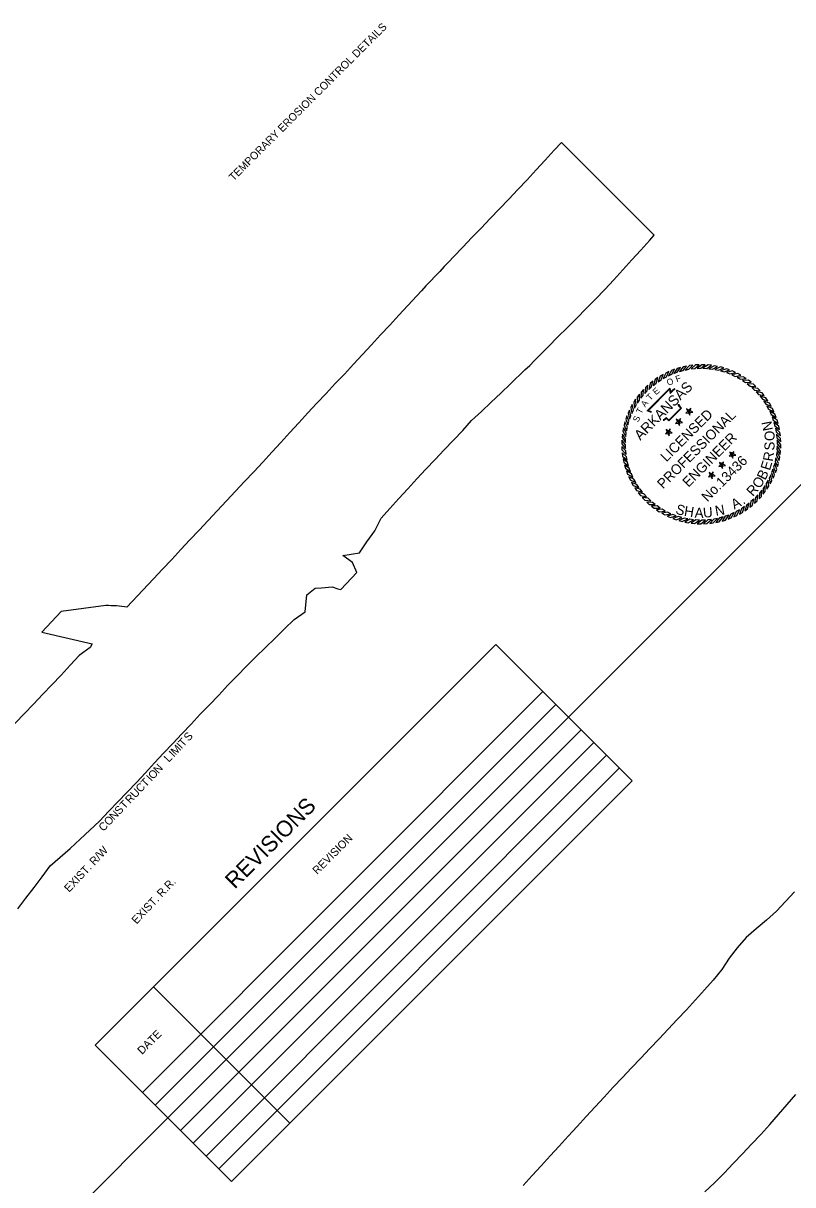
# Model space of a CAD drawing. Extents: x 1377291 to 1378879, y 1932405 to 1934097.
# Drawn here: x 1377982 to 1378559, y 1933226 to 1934097 of the extents above; entities that cross this region are included whole.
import ezdxf

# ---------------------------------------------------------------- set-up
doc = ezdxf.new("R2010")
doc.units = 0
for name, color, linetype in [('1', 7, 'Continuous'), ('Default', 7, 'Continuous'), ('G-ANNO-SYMB', 7, 'Continuous'), ('R_Draft', 7, 'Continuous'), ('R_NO PLOT', 7, 'Continuous')]:
    doc.layers.add(name, color=color, linetype=linetype)

msp = doc.modelspace()

# ---------------------------------------------------------------- linework, layer by layer
at = {"layer": '1'}
for p, q in [((1378390.79, 1933576.64), (1378603.63, 1933789.47)), ((1377887.91, 1933073.76), (1378090.27, 1933276.12))]:
    msp.add_line(p, q, dxfattribs=at)
at = {"layer": 'Default'}
for p, q in [((1378035.83, 1933330.56), (1378336.35, 1933631.08)), ((1378336.35, 1933631.08), (1378438.52, 1933528.91)), ((1378071.18, 1933295.21), (1378371.7, 1933595.73)), ((1378080.73, 1933285.66), (1378381.25, 1933586.18)), ((1378090.27, 1933276.12), (1378390.79, 1933576.64)), ((1378099.82, 1933266.57), (1378400.34, 1933567.09)), ((1378099.82, 1933266.57), (1378400.34, 1933567.09)), ((1378109.37, 1933257.02), (1378409.89, 1933557.55)), ((1378118.91, 1933247.48), (1378419.43, 1933548)), ((1378128.46, 1933237.93), (1378428.98, 1933538.45)), ((1378138, 1933228.39), (1378438.52, 1933528.91)), ((1378079.53, 1933374.27), (1378181.71, 1933272.09)), ((1378035.83, 1933330.56), (1378138, 1933228.39))]:
    msp.add_line(p, q, dxfattribs=at)
at = {"layer": 'G-ANNO-SYMB'}
for points in [[(1378466.07, 1933835.66), (1378463.76, 1933834.56), (1378461.82, 1933830.41), (1378464.25, 1933831.75)], [(1378470.42, 1933837.4), (1378468.02, 1933836.49), (1378465.77, 1933832.51), (1378468.3, 1933833.65)], [(1378474.89, 1933838.8), (1378472.43, 1933838.08), (1378469.87, 1933834.29), (1378472.48, 1933835.23)], [(1378479.46, 1933839.85), (1378476.95, 1933839.32), (1378474.1, 1933835.74), (1378476.77, 1933836.47)], [(1378484.09, 1933840.53), (1378481.55, 1933840.2), (1378478.43, 1933836.86), (1378481.15, 1933837.38)], [(1378488.77, 1933840.85), (1378486.2, 1933840.72), (1378482.83, 1933837.63), (1378485.59, 1933837.94)], [(1378493.45, 1933840.8), (1378490.89, 1933840.87), (1378487.28, 1933838.06), (1378490.05, 1933838.14)], [(1378498.12, 1933840.38), (1378495.56, 1933840.66), (1378491.75, 1933838.13), (1378494.52, 1933838)], [(1378502.73, 1933839.6), (1378500.21, 1933840.07), (1378496.21, 1933837.86), (1378498.96, 1933837.51)], [(1378507.28, 1933838.46), (1378504.8, 1933839.13), (1378500.64, 1933837.23), (1378503.35, 1933836.67)], [(1378511.72, 1933836.96), (1378509.3, 1933837.82), (1378505, 1933836.26), (1378507.67, 1933835.49)], [(1378516.03, 1933835.12), (1378513.68, 1933836.17), (1378509.28, 1933834.95), (1378511.87, 1933833.97)], [(1378520.18, 1933832.95), (1378517.92, 1933834.18), (1378513.44, 1933833.31), (1378515.94, 1933832.13)], [(1378450.44, 1933825.45), (1378448.58, 1933823.69), (1378448.02, 1933819.15), (1378449.92, 1933821.17)], [(1378454.04, 1933828.46), (1378452.04, 1933826.85), (1378451.13, 1933822.37), (1378453.18, 1933824.23)], [(1378457.86, 1933831.17), (1378455.74, 1933829.72), (1378454.48, 1933825.33), (1378456.67, 1933827.03)], [(1378461.88, 1933833.57), (1378459.65, 1933832.3), (1378458.05, 1933828.01), (1378460.37, 1933829.54)], [(1378524.14, 1933830.46), (1378522, 1933831.86), (1378517.45, 1933831.35), (1378519.86, 1933829.97)], [(1378527.9, 1933827.67), (1378525.87, 1933829.23), (1378521.3, 1933829.07), (1378523.6, 1933827.52)], [(1378531.43, 1933824.59), (1378529.53, 1933826.31), (1378524.96, 1933826.51), (1378527.13, 1933824.78)], [(1378444.02, 1933818.65), (1378442.45, 1933816.62), (1378442.61, 1933812.05), (1378444.17, 1933814.34)], [(1378447.1, 1933822.18), (1378445.38, 1933820.27), (1378445.18, 1933815.71), (1378446.91, 1933817.87)], [(1378534.71, 1933821.24), (1378532.95, 1933823.11), (1378528.41, 1933823.66), (1378530.43, 1933821.77)], [(1378537.71, 1933817.65), (1378536.1, 1933819.64), (1378531.62, 1933820.55), (1378533.49, 1933818.51)], [(1378540.43, 1933813.83), (1378538.98, 1933815.94), (1378534.58, 1933817.2), (1378536.28, 1933815.02)], [(1378438.73, 1933810.92), (1378437.5, 1933808.67), (1378438.38, 1933804.18), (1378439.56, 1933806.69)], [(1378441.22, 1933814.89), (1378439.82, 1933812.74), (1378440.34, 1933808.2), (1378441.71, 1933810.6)], [(1378481.39, 1933805.73), (1378482.31, 1933806.2), (1378482.62, 1933808.16), (1378481.22, 1933806.76)], [(1378542.83, 1933809.81), (1378541.55, 1933812.03), (1378537.27, 1933813.63), (1378538.79, 1933811.32)], [(1378544.91, 1933805.61), (1378543.81, 1933807.93), (1378539.67, 1933809.86), (1378541.01, 1933807.43)], [(1378434.72, 1933802.46), (1378433.86, 1933800.04), (1378435.42, 1933795.75), (1378436.2, 1933798.41)], [(1378436.56, 1933806.77), (1378435.51, 1933804.43), (1378436.73, 1933800.02), (1378437.71, 1933802.61)], [(1378473.67, 1933798.01), (1378473.51, 1933799.04), (1378471.74, 1933799.94), (1378472.64, 1933798.18)], [(1378473.67, 1933798.01), (1378474.6, 1933798.49), (1378474.91, 1933800.44), (1378473.51, 1933799.04)], [(1378481.39, 1933805.73), (1378480.36, 1933805.89), (1378478.96, 1933804.49), (1378480.91, 1933804.8)], [(1378481.39, 1933805.73), (1378481.22, 1933806.76), (1378479.46, 1933807.65), (1378480.36, 1933805.89)], [(1378481.39, 1933805.73), (1378480.91, 1933804.8), (1378481.81, 1933803.03), (1378482.12, 1933804.99)], [(1378481.39, 1933805.73), (1378482.12, 1933804.99), (1378484.08, 1933805.3), (1378482.31, 1933806.2)], [(1378546.66, 1933801.26), (1378545.75, 1933803.66), (1378541.77, 1933805.91), (1378542.91, 1933803.39)], [(1378548.06, 1933796.79), (1378547.34, 1933799.25), (1378543.55, 1933801.81), (1378544.49, 1933799.2)], [(1378432.09, 1933793.48), (1378431.61, 1933790.96), (1378433.83, 1933786.96), (1378434.18, 1933789.71)], [(1378433.23, 1933798.02), (1378432.56, 1933795.54), (1378434.45, 1933791.38), (1378435.02, 1933794.1)], [(1378465.96, 1933790.3), (1378464.93, 1933790.46), (1378463.53, 1933789.06), (1378465.49, 1933789.37)], [(1378465.96, 1933790.3), (1378465.8, 1933791.33), (1378464.03, 1933792.23), (1378464.93, 1933790.46)], [(1378465.96, 1933790.3), (1378465.49, 1933789.37), (1378466.39, 1933787.6), (1378466.7, 1933789.56)], [(1378465.96, 1933790.3), (1378466.89, 1933790.77), (1378467.2, 1933792.73), (1378465.8, 1933791.33)], [(1378465.96, 1933790.3), (1378466.7, 1933789.56), (1378468.65, 1933789.87), (1378466.89, 1933790.77)], [(1378473.67, 1933798.01), (1378472.64, 1933798.18), (1378471.24, 1933796.77), (1378473.2, 1933797.08)], [(1378473.67, 1933798.01), (1378473.2, 1933797.08), (1378474.1, 1933795.32), (1378474.41, 1933797.28)], [(1378473.67, 1933798.01), (1378474.41, 1933797.28), (1378476.37, 1933797.59), (1378474.6, 1933798.49)], [(1378549.11, 1933792.23), (1378548.58, 1933794.74), (1378545, 1933797.58), (1378545.73, 1933794.91)], [(1378549.79, 1933787.59), (1378549.46, 1933790.14), (1378546.12, 1933793.26), (1378546.64, 1933790.53)], [(1378430.89, 1933784.19), (1378430.81, 1933781.63), (1378433.63, 1933778.03), (1378433.54, 1933780.8)], [(1378431.3, 1933788.86), (1378431.03, 1933786.31), (1378433.55, 1933782.49), (1378433.68, 1933785.26)], [(1378550.11, 1933782.92), (1378549.98, 1933785.48), (1378546.89, 1933788.85), (1378547.19, 1933786.1)], [(1378550.06, 1933778.23), (1378550.13, 1933780.8), (1378547.31, 1933784.4), (1378547.4, 1933781.63)], [(1378430.84, 1933779.51), (1378430.96, 1933776.95), (1378434.05, 1933773.58), (1378433.75, 1933776.33)], [(1378431.15, 1933774.84), (1378431.48, 1933772.29), (1378434.83, 1933769.17), (1378434.31, 1933771.89)], [(1378513.69, 1933773.42), (1378512.66, 1933773.59), (1378511.26, 1933772.19), (1378513.22, 1933772.5)], [(1378513.69, 1933773.42), (1378513.53, 1933774.45), (1378511.76, 1933775.35), (1378512.66, 1933773.59)], [(1378513.69, 1933773.42), (1378513.22, 1933772.5), (1378514.12, 1933770.73), (1378514.43, 1933772.69)], [(1378513.69, 1933773.42), (1378514.62, 1933773.9), (1378514.93, 1933775.85), (1378513.53, 1933774.45)], [(1378513.69, 1933773.42), (1378514.43, 1933772.69), (1378516.38, 1933773), (1378514.62, 1933773.9)], [(1378548.86, 1933768.95), (1378549.33, 1933771.47), (1378547.11, 1933775.47), (1378546.77, 1933772.72)], [(1378549.64, 1933773.57), (1378549.91, 1933776.12), (1378547.39, 1933779.93), (1378547.26, 1933777.16)], [(1378431.84, 1933770.2), (1378432.36, 1933767.69), (1378435.94, 1933764.84), (1378435.21, 1933767.52)], [(1378432.88, 1933765.63), (1378433.6, 1933763.17), (1378437.4, 1933760.62), (1378436.46, 1933763.22)], [(1378505.97, 1933765.71), (1378504.95, 1933765.87), (1378503.54, 1933764.47), (1378505.5, 1933764.78)], [(1378505.97, 1933765.71), (1378505.81, 1933766.74), (1378504.05, 1933767.64), (1378504.95, 1933765.87)], [(1378505.97, 1933765.71), (1378505.5, 1933764.78), (1378506.4, 1933763.02), (1378506.71, 1933764.97)], [(1378505.97, 1933765.71), (1378506.9, 1933766.18), (1378507.21, 1933768.14), (1378505.81, 1933766.74)], [(1378505.97, 1933765.71), (1378506.71, 1933764.97), (1378508.67, 1933765.28), (1378506.9, 1933766.18)], [(1378546.22, 1933759.97), (1378547.08, 1933762.38), (1378545.52, 1933766.68), (1378544.74, 1933764.02)], [(1378547.71, 1933764.41), (1378548.38, 1933766.88), (1378546.49, 1933771.04), (1378545.93, 1933768.33)], [(1378434.28, 1933761.16), (1378435.2, 1933758.77), (1378439.18, 1933756.51), (1378438.03, 1933759.04)], [(1378436.03, 1933756.82), (1378437.13, 1933754.5), (1378441.27, 1933752.57), (1378439.94, 1933755)], [(1378498.26, 1933758), (1378497.23, 1933758.16), (1378495.83, 1933756.76), (1378497.79, 1933757.07)], [(1378498.26, 1933758), (1378498.1, 1933759.03), (1378496.33, 1933759.92), (1378497.23, 1933758.16)], [(1378498.26, 1933758), (1378497.79, 1933757.07), (1378498.69, 1933755.3), (1378499, 1933757.26)], [(1378498.26, 1933758), (1378499.19, 1933758.47), (1378499.5, 1933760.43), (1378498.1, 1933759.03)], [(1378498.26, 1933758), (1378499, 1933757.26), (1378500.95, 1933757.57), (1378499.19, 1933758.47)], [(1378542.21, 1933751.51), (1378543.44, 1933753.76), (1378542.57, 1933758.25), (1378541.39, 1933755.74)], [(1378544.38, 1933755.66), (1378545.43, 1933758), (1378544.21, 1933762.41), (1378543.23, 1933759.81)], [(1378438.11, 1933752.62), (1378439.39, 1933750.4), (1378443.67, 1933748.79), (1378442.15, 1933751.11)], [(1378440.51, 1933748.6), (1378441.96, 1933746.48), (1378446.36, 1933745.22), (1378444.66, 1933747.41)], [(1378533.84, 1933740.25), (1378535.57, 1933742.15), (1378535.77, 1933746.72), (1378534.03, 1933744.56)], [(1378536.93, 1933743.78), (1378538.49, 1933745.81), (1378538.33, 1933750.38), (1378536.77, 1933748.09)], [(1378539.72, 1933747.54), (1378541.12, 1933749.69), (1378540.6, 1933754.23), (1378539.23, 1933751.82)], [(1378443.23, 1933744.78), (1378444.84, 1933742.78), (1378449.32, 1933741.87), (1378447.45, 1933743.92)], [(1378446.23, 1933741.19), (1378447.99, 1933739.32), (1378452.53, 1933738.77), (1378450.51, 1933740.66)], [(1378526.9, 1933733.97), (1378528.9, 1933735.58), (1378529.81, 1933740.06), (1378527.76, 1933738.2)], [(1378530.5, 1933736.97), (1378532.36, 1933738.74), (1378532.92, 1933743.27), (1378531.02, 1933741.25)], [(1378449.51, 1933737.84), (1378451.41, 1933736.12), (1378455.98, 1933735.92), (1378453.82, 1933737.65)], [(1378453.04, 1933734.76), (1378455.07, 1933733.19), (1378459.64, 1933733.35), (1378457.35, 1933734.91)], [(1378456.8, 1933731.97), (1378458.95, 1933730.56), (1378463.49, 1933731.08), (1378461.08, 1933732.45)], [(1378460.77, 1933729.48), (1378463.02, 1933728.25), (1378467.51, 1933729.12), (1378465, 1933730.3)], [(1378510.52, 1933725.02), (1378512.92, 1933725.94), (1378515.17, 1933729.92), (1378512.64, 1933728.78)], [(1378514.87, 1933726.77), (1378517.19, 1933727.87), (1378519.12, 1933732.01), (1378516.69, 1933730.68)], [(1378519.06, 1933728.85), (1378521.29, 1933730.13), (1378522.89, 1933734.41), (1378520.57, 1933732.89)], [(1378523.08, 1933731.26), (1378525.2, 1933732.71), (1378526.46, 1933737.1), (1378524.27, 1933735.4)], [(1378464.92, 1933727.3), (1378467.26, 1933726.26), (1378471.66, 1933727.48), (1378469.07, 1933728.46)], [(1378469.22, 1933725.47), (1378471.64, 1933724.6), (1378475.94, 1933726.17), (1378473.28, 1933726.94)], [(1378473.66, 1933723.97), (1378476.14, 1933723.3), (1378480.3, 1933725.2), (1378477.59, 1933725.76)], [(1378478.21, 1933722.83), (1378480.73, 1933722.36), (1378484.73, 1933724.57), (1378481.98, 1933724.92)], [(1378482.83, 1933722.05), (1378485.38, 1933721.77), (1378489.19, 1933724.3), (1378486.42, 1933724.43)], [(1378487.49, 1933721.63), (1378490.06, 1933721.56), (1378493.66, 1933724.37), (1378490.89, 1933724.28)], [(1378492.18, 1933721.58), (1378494.74, 1933721.71), (1378498.11, 1933724.8), (1378495.35, 1933724.49)], [(1378496.85, 1933721.9), (1378499.39, 1933722.23), (1378502.51, 1933725.57), (1378499.79, 1933725.05)], [(1378501.48, 1933722.58), (1378503.99, 1933723.11), (1378506.84, 1933726.69), (1378504.17, 1933725.95)], [(1378506.05, 1933723.62), (1378508.51, 1933724.35), (1378511.07, 1933728.14), (1378508.46, 1933727.2)]]:
    msp.add_lwpolyline(points, close=True, dxfattribs=at)
for points in [[(1378453.09, 1933805.07), (1378449.98, 1933806.22), (1378466.99, 1933823.24), (1378467.35, 1933820.04), (1378468.49, 1933821.21), (1378469.45, 1933822.19), (1378470.52, 1933823.05)], [(1378453.23, 1933805.43), (1378450.67, 1933806.37), (1378466.7, 1933822.42), (1378467.06, 1933819.2), (1378468.77, 1933820.94), (1378469.7, 1933821.9), (1378470.75, 1933822.75)], [(1378473.58, 1933811.29), (1378473.52, 1933810.77), (1378473.78, 1933810.32), (1378474.56, 1933809.34), (1378475.74, 1933808.16), (1378466.24, 1933798.66), (1378464.65, 1933800.25), (1378464.3, 1933800.61), (1378463.8, 1933800.34), (1378462.45, 1933798.99), (1378461.84, 1933799.11)], [(1378473.2, 1933811.33), (1378473.13, 1933810.68), (1378473.46, 1933810.1), (1378474.28, 1933809.08), (1378475.2, 1933808.16), (1378466.24, 1933799.2), (1378464.92, 1933800.52), (1378464.37, 1933801.07), (1378463.57, 1933800.65), (1378462.32, 1933799.4), (1378461.92, 1933799.49)]]:
    msp.add_lwpolyline(points, dxfattribs=at)
at = {"layer": 'R_NO PLOT'}
for p, q in [((1378043.74, 1933660.2), (1378010.12, 1933655.71)), ((1378033.6, 1933631.58), (1378032.08, 1933628.8))]:
    msp.add_line(p, q, dxfattribs=at)
for points in [[(1378455.1, 1933938), (1378385.59, 1934007.51), (1378380.13, 1934001.59), (1378373.33, 1933994.25), (1378366.54, 1933986.91), (1378359.74, 1933979.57), (1378352.94, 1933972.25), (1378346.03, 1933965.01), (1378339.12, 1933957.78), (1378332.2, 1933950.57), (1378325.28, 1933943.35), (1378318.38, 1933936.11), (1378311.49, 1933928.86), (1378304.6, 1933921.62), (1378301.15, 1933917.99)], [(1378221.56, 1933697.7), (1378233.93, 1933699.8), (1378239.64, 1933708.16), (1378245.48, 1933716.39), (1378250.21, 1933725.67), (1378256.89, 1933733.12), (1378263.67, 1933740.47), (1378270.39, 1933747.87), (1378277.11, 1933755.28), (1378283.89, 1933762.63), (1378290.85, 1933769.82), (1378297.68, 1933777.11), (1378304.59, 1933784.35), (1378311.48, 1933791.59), (1378318.16, 1933799.04), (1378325.48, 1933805.88), (1378332.77, 1933812.75), (1378340.06, 1933819.63), (1378347.34, 1933826.5), (1378350.95, 1933829.98), (1378354.58, 1933833.42), (1378358.2, 1933836.89), (1378361.79, 1933840.37), (1378365.33, 1933843.91), (1378368.85, 1933847.46), (1378372.37, 1933851.01), (1378375.9, 1933854.56), (1378382.94, 1933861.67), (1378389.99, 1933868.76), (1378397.05, 1933875.85), (1378404.1, 1933882.95), (1378411.16, 1933890.04), (1378418.09, 1933897.24), (1378424.85, 1933904.61), (1378431.6, 1933911.99), (1378438.36, 1933919.37), (1378445.11, 1933926.75), (1378451.78, 1933934.2), (1378455.1, 1933938)], [(1378301.15, 1933917.99), (1378297.68, 1933914.4), (1378294.2, 1933910.8), (1378290.73, 1933907.2), (1378287.32, 1933903.54), (1378283.92, 1933899.88), (1378280.52, 1933896.22), (1378277.11, 1933892.55), (1378270.31, 1933885.22), (1378263.5, 1933877.9), (1378256.7, 1933870.57), (1378249.93, 1933863.21), (1378243.16, 1933855.85), (1378236.39, 1933848.49), (1378229.61, 1933841.13), (1378222.85, 1933833.76), (1378215.83, 1933826.64), (1378208.95, 1933819.38), (1378202.15, 1933812.05), (1378195.38, 1933804.69), (1378188.58, 1933797.35), (1378181.79, 1933790.02), (1378175.04, 1933782.64), (1378168.29, 1933775.25), (1378161.55, 1933767.86), (1378154.74, 1933760.55), (1378147.9, 1933753.24), (1378141.06, 1933745.95), (1378134.21, 1933738.66), (1378127.37, 1933731.38), (1378120.52, 1933724.09), (1378113.67, 1933716.8), (1378106.84, 1933709.49), (1378099.99, 1933702.21), (1378093.16, 1933694.9), (1378086.33, 1933687.6), (1378079.51, 1933680.29), (1378059.62, 1933659.04)], [(1378232.15, 1933685.1), (1378228.83, 1933692.53), (1378221.56, 1933697.7)], [(1378205.53, 1933673.59), (1378213.58, 1933674.24), (1378217.76, 1933672.69), (1378219.95, 1933672.17), (1378232.15, 1933685.1)], [(1378194.5, 1933668.24), (1378200.76, 1933673.22), (1378205.53, 1933673.59)], [(1377977.76, 1933432.8), (1377983.83, 1933440.81), (1377989.89, 1933448.84), (1377996.09, 1933456.74), (1378001.89, 1933465.01), (1378009.56, 1933471.52), (1378017.08, 1933478.18), (1378024.39, 1933485.03), (1378031.76, 1933491.83), (1378039.05, 1933498.7), (1378045.93, 1933505.96), (1378052.83, 1933513.2), (1378059.77, 1933520.4), (1378066.64, 1933527.66), (1378073.59, 1933534.85), (1378080.32, 1933542.25), (1378087.13, 1933549.58), (1378094.04, 1933556.81), (1378100.84, 1933564.14), (1378107.69, 1933571.42), (1378114.43, 1933578.81), (1378121.48, 1933585.91), (1378128.41, 1933593.12), (1378135.23, 1933600.44), (1378142.2, 1933607.61), (1378149.18, 1933614.77), (1378156.31, 1933621.79), (1378163.45, 1933628.81), (1378170.66, 1933635.75), (1378177.82, 1933642.74), (1378185, 1933649.72), (1378193.33, 1933655.62), (1378194.5, 1933668.24)], [(1378010.12, 1933655.71), (1377995.68, 1933640.37), (1378033.6, 1933631.58)], [(1378032.08, 1933628.8), (1378023.82, 1933622.84), (1378017.02, 1933615.51), (1378010.21, 1933608.18), (1378003.34, 1933600.92), (1377996.38, 1933593.74), (1377989.58, 1933586.41), (1377982.61, 1933579.24), (1377975.66, 1933572.04), (1377968.8, 1933564.76), (1377962.03, 1933557.41), (1377955.24, 1933550.06), (1377948.47, 1933542.7), (1377941.65, 1933535.39)], [(1378560.44, 1933445.69), (1378553.61, 1933438.39), (1378546.8, 1933431.06), (1378539.34, 1933424.35), (1378531.76, 1933417.75), (1378524.08, 1933411.25), (1378517.49, 1933403.71), (1378511.35, 1933395.76), (1378505.8, 1933387.25), (1378499.47, 1933379.48), (1378492.8, 1933372.03), (1378486.14, 1933364.56), (1378479.36, 1933357.21), (1378472.49, 1933349.94), (1378465.63, 1933342.67), (1378458.81, 1933335.35), (1378451.96, 1933328.06), (1378445.06, 1933320.83), (1378438.17, 1933313.58), (1378431.31, 1933306.3), (1378424.45, 1933299.03), (1378417.59, 1933291.75), (1378410.81, 1933284.4), (1378404.03, 1933277.05), (1378397.25, 1933269.7), (1378390.49, 1933262.33), (1378383.75, 1933254.94), (1378377, 1933247.56), (1378370.27, 1933240.16), (1378363.52, 1933232.79), (1378356.74, 1933225.43)], [(1378493.15, 1933220.69), (1378500.49, 1933227.52), (1378507.57, 1933234.59), (1378514.46, 1933241.83), (1378521.37, 1933249.07), (1378528.22, 1933256.35), (1378535.13, 1933263.58), (1378541.8, 1933271.04), (1378548.36, 1933278.59), (1378554.92, 1933286.15), (1378561.49, 1933293.7)]]:
    msp.add_lwpolyline(points, dxfattribs=at)
msp.add_arc((1378045, 1933568.21), 91.99, 80.85932, 90.78815, dxfattribs=at)

# ---------------------------------------------------------------- texts
at = {"layer": '1'}
msp.add_text('TEMPORARY EROSION CONTROL DETAILS', height=5.862, rotation=45, dxfattribs=at).set_placement((1378139.56, 1933978.11))
at = {"layer": 'Default'}
for s, height, p in [('REVISIONS', 12, (1378140.48, 1933447.24)), ('REVISION', 6, (1378202.34, 1933458.19)), ('DATE', 6, (1378070.93, 1933323.24))]:
    msp.add_text(s, height=height, rotation=45, dxfattribs=at).set_placement(p)
at = {"layer": 'G-ANNO-SYMB'}
for s, height, rotation, p in [('ARKANSAS', 7.747, 45, (1378444.72, 1933783.66)), ('O', 4.75, 26.2218, (1378465.84, 1933824.85)), ('F', 4.75, 20.36282, (1378472.14, 1933827.6)), ('T', 4.75, 46.47887, (1378452.15, 1933813.65)), ('E', 4.75, 41.67203, (1378456.54, 1933817.85)), ('T', 4.75, 61.90148, (1378445.47, 1933803.51)), ('A', 4.75, 53.67877, (1378448.48, 1933808.65)), ('S', 4.75, 64.77256, (1378443.12, 1933797.33)), ('PROFESSIONAL', 7.5, 45, (1378461.81, 1933747.25)), ('LICENSED', 7.5, 45, (1378464.3, 1933767.48)), ('N', 7.5, 101.10067, (1378544.33, 1933792.04)), ('O', 7.5, 89.77573, (1378545.43, 1933783.58)), ('ENGINEER', 7.5, 45, (1378480.78, 1933748.48)), ('S', 7.5, 88.48784, (1378545.3, 1933776.42)), ('R', 7.5, 80.65967, (1378544.03, 1933767.94)), ('No.13436', 7.47, 45, (1378495.09, 1933737.51)), ('E', 7.5, 72.83149, (1378541.89, 1933761.11)), ('O', 7.5, 56.42961, (1378534.26, 1933747.39)), ('B', 7.5, 63.88501, (1378538.45, 1933753.83)), ('R', 7.5, 48.22866, (1378529.18, 1933741.62)), ('A', 7.5, 28.09908, (1378515.25, 1933732.12)), ('S', 7.5, 343.16364, (1378470.61, 1933729.4)), ('H', 7.5, 350.61905, (1378477.19, 1933727.66)), ('A', 7.5, 358.44722, (1378485.4, 1933726.19)), ('U', 7.5, 5.90262, (1378492.16, 1933726.03)), ('N', 7.5, 9.93262, (1378501.45, 1933727.43)), ('.', 7.5, 36.30002, (1378522.01, 1933735.79))]:
    msp.add_text(s, height=height, rotation=rotation, dxfattribs=at).set_placement(p)
at = {"layer": 'R_Draft'}
for s, rotation, p in [('S', 46.7261, (1378105.86, 1933558.09)), ('M', 46.31286, (1378096.07, 1933547.65)), ('I', 47.13711, (1378100.56, 1933552.37)), ('T', 47.13711, (1378101.91, 1933553.83)), ('L', 46.31286, (1378090.98, 1933542.32)), ('I', 46.31286, (1378094.7, 1933546.22)), ('N', 47.72308, (1378083.2, 1933533.82)), ('T', 45.96827, (1378073.68, 1933523.72)), ('I', 47.72308, (1378077.92, 1933528.02)), ('O', 47.72308, (1378079.26, 1933529.49)), ('U', 46.59205, (1378065.85, 1933515.48)), ('C', 46.59205, (1378069.81, 1933519.66)), ('T', 46.04023, (1378057.82, 1933507.13)), ('R', 46.04023, (1378061.88, 1933511.35)), ('N', 46.38494, (1378050.02, 1933498.95)), ('S', 46.38494, (1378053.93, 1933503.05)), ('C', 43.26026, (1378041.72, 1933490.49)), ('O', 46.55661, (1378046.01, 1933494.7)), ('EXIST. R/W', 46.66069, (1378016.19, 1933444.87)), ('EXIST. R.R.', 46.66069, (1378066.77, 1933420.98))]:
    msp.add_text(s, height=6, rotation=rotation, dxfattribs=at).set_placement(p)

doc.saveas('drawing.dxf')
